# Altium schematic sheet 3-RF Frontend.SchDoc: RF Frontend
size B; CompanyName: NGRF; Address1: 2130 Howard Drive W; Address2: North Mankato, MN 56003; Address3: www.nextgenrf.com; Revision: 2; SheetNumber: 3; SheetTotal: 7; ProjName: BytePipe X9002_HDK
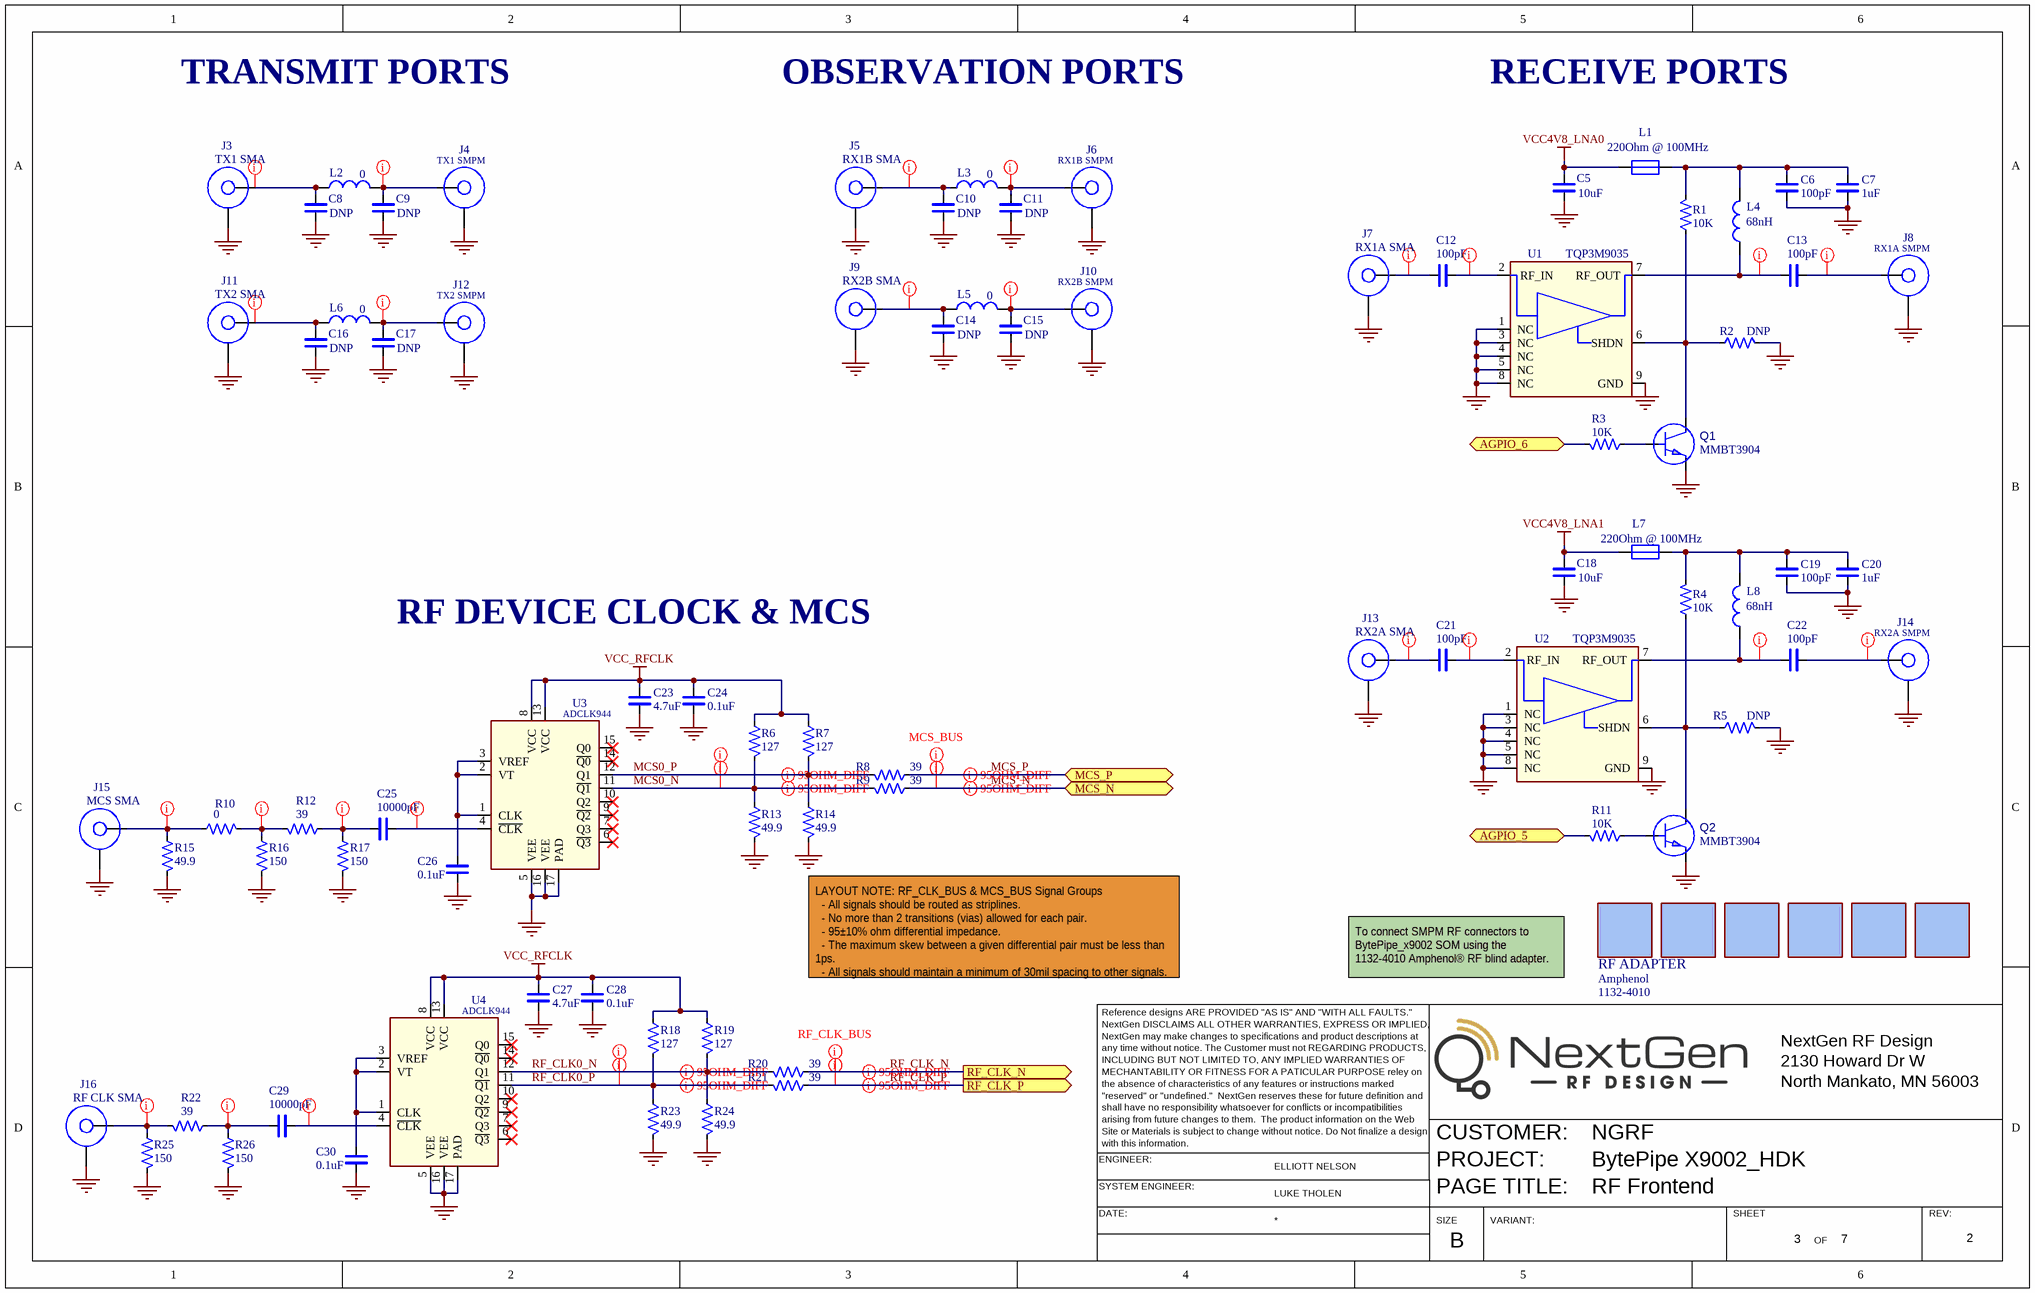
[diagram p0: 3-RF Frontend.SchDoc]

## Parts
B3  RF ADAPTER  OEM NAME: Amphenol  OEM#: 1132-4010
B4  RF ADAPTER  (value not drawn)
B5  RF ADAPTER  (value not drawn)
B6  RF ADAPTER  (value not drawn)
B7  RF ADAPTER  (value not drawn)
B8  RF ADAPTER  (value not drawn)
C5  value 10uF  [SM/0402/CAP]  (hidden comment: CAP_CERAMIC_0402)
C6  value 100pF  [SM/0402/CAP]  (hidden comment: CAP_CERAMIC_0402)
C7  value 1uF  [SM/0402/CAP]  (hidden comment: CAP_CERAMIC_0402)
C8  value DNP  [SM/0402/CAP]  (hidden comment: CAP_CERAMIC_0402)
C9  value DNP  [SM/0402/CAP]  (hidden comment: CAP_CERAMIC_0402)
C10  value DNP  [SM/0402/CAP]  (hidden comment: CAP_CERAMIC_0402)
C11  value DNP  [SM/0402/CAP]  (hidden comment: CAP_CERAMIC_0402)
C12  value 100pF  [SM/0402/CAP]  (hidden comment: CAP_CERAMIC_0402)
C13  value 100pF  [SM/0402/CAP]  (hidden comment: CAP_CERAMIC_0402)
C14  value DNP  [SM/0402/CAP]  (hidden comment: CAP_CERAMIC_0402)
C15  value DNP  [SM/0402/CAP]  (hidden comment: CAP_CERAMIC_0402)
C16  value DNP  [SM/0402/CAP]  (hidden comment: CAP_CERAMIC_0402)
C17  value DNP  [SM/0402/CAP]  (hidden comment: CAP_CERAMIC_0402)
C18  value 10uF  [SM/0402/CAP]  (hidden comment: CAP_CERAMIC_0402)
C19  value 100pF  [SM/0402/CAP]  (hidden comment: CAP_CERAMIC_0402)
C20  value 1uF  [SM/0402/CAP]  (hidden comment: CAP_CERAMIC_0402)
C21  value 100pF  [SM/0402/CAP]  (hidden comment: CAP_CERAMIC_0402)
C22  value 100pF  [SM/0402/CAP]  (hidden comment: CAP_CERAMIC_0402)
C23  value 4.7uF  [SM/0402/CAP]  (hidden comment: CAP_CERAMIC_0402)
C24  value 0.1uF  [SM/0402/CAP]  (hidden comment: CAP_CERAMIC_0402)
C25  value 10000pF  [SM/0402/CAP]  (hidden comment: CAP_CERAMIC_0402)
C26  value 0.1uF  [SM/0402/CAP]  (hidden comment: CAP_CERAMIC_0402)
C27  value 4.7uF  [SM/0402/CAP]  (hidden comment: CAP_CERAMIC_0402)
C28  value 0.1uF  [SM/0402/CAP]  (hidden comment: CAP_CERAMIC_0402)
C29  value 10000pF  [SM/0402/CAP]  (hidden comment: CAP_CERAMIC_0402)
C30  value 0.1uF  [SM/0402/CAP]  (hidden comment: CAP_CERAMIC_0402)
J3  value TX1 SMA  [SM/CON/RF/SMA/BRD-EDGE_C]  (hidden comment: CON_RF_SMA_BRD-EDGE_C)
J4  value TX1 SMPM  [SM/CON/RF/SMPM/VERT_A]  (hidden comment: CON_RF_SMPM_SMT_AMPHENOL)
J5  value RX1B SMA  [SM/CON/RF/SMA/BRD-EDGE_C]  (hidden comment: CON_RF_SMA_BRD-EDGE_C)
J6  value RX1B SMPM  [SM/CON/RF/SMPM/VERT_A]  (hidden comment: CON_RF_SMPM_SMT_AMPHENOL)
J7  value RX1A SMA  [SM/CON/RF/SMA/BRD-EDGE_C]  (hidden comment: CON_RF_SMA_BRD-EDGE_C)
J8  value RX1A SMPM  [SM/CON/RF/SMPM/VERT_A]  (hidden comment: CON_RF_SMPM_SMT_AMPHENOL)
J9  value RX2B SMA  [SM/CON/RF/SMA/BRD-EDGE_C]  (hidden comment: CON_RF_SMA_BRD-EDGE_C)
J10  value RX2B SMPM  [SM/CON/RF/SMPM/VERT_A]  (hidden comment: CON_RF_SMPM_SMT_AMPHENOL)
J11  value TX2 SMA  [SM/CON/RF/SMA/BRD-EDGE_C]  (hidden comment: CON_RF_SMA_BRD-EDGE_C)
J12  value TX2 SMPM  [SM/CON/RF/SMPM/VERT_A]  (hidden comment: CON_RF_SMPM_SMT_AMPHENOL)
J13  value RX2A SMA  [SM/CON/RF/SMA/BRD-EDGE_C]  (hidden comment: CON_RF_SMA_BRD-EDGE_C)
J14  value RX2A SMPM  [SM/CON/RF/SMPM/VERT_A]  (hidden comment: CON_RF_SMPM_SMT_AMPHENOL)
J15  value MCS SMA  [SM/CON/RF/SMA/BRD-EDGE_C]  (hidden comment: CON_RF_SMA_BRD-EDGE_C)
J16  value RF CLK SMA  [SM/CON/RF/SMA/BRD-EDGE_C]  (hidden comment: CON_RF_SMA_BRD-EDGE_C)
L1  value 220Ohm @ 100MHz  [SM/0603]  (hidden comment: FERRITE_0603_A)
L2  value 0  [SM/0402]  (hidden comment: IND_0402)
L3  value 0  [SM/0402]  (hidden comment: IND_0402)
L4  value 68nH  [SM/0603]  (hidden comment: IND_0603)
L5  value 0  [SM/0402]  (hidden comment: IND_0402)
L6  value 0  [SM/0402]  (hidden comment: IND_0402)
L7  value 220Ohm @ 100MHz  [SM/0603]  (hidden comment: FERRITE_0603_A)
L8  value 68nH  [SM/0603]  (hidden comment: IND_0603)
Q1  value MMBT3904  [SM/SOT23_A]  (hidden comment: TRANSISTOR_NPN_SOT23)
Q2  value MMBT3904  [SM/SOT23_A]  (hidden comment: TRANSISTOR_NPN_SOT23)
R1  value 10K  [SM/0402/RES]  (hidden comment: RES_0402_A)
R2  value DNP  [SM/0402/RES]  (hidden comment: RES_0402_A)
R3  value 10K  [SM/0402/RES]  (hidden comment: RES_0402_A)
R4  value 10K  [SM/0402/RES]  (hidden comment: RES_0402_A)
R5  value DNP  [SM/0402/RES]  (hidden comment: RES_0402_A)
R6  value 127  [SM/0402/RES]  (hidden comment: RES_0402_A)
R7  value 127  [SM/0402/RES]  (hidden comment: RES_0402_A)
R8  value 39  [SM/0402/RES]  (hidden comment: RES_0402_A)
R9  value 39  [SM/0402/RES]  (hidden comment: RES_0402_A)
R10  value 0  [SM/0402/RES]  (hidden comment: RES_0402_A)
R11  value 10K  [SM/0402/RES]  (hidden comment: RES_0402_A)
R12  value 39  [SM/0402/RES]  (hidden comment: RES_0402_A)
R13  value 49.9  [SM/0402/RES]  (hidden comment: RES_0402_A)
R14  value 49.9  [SM/0402/RES]  (hidden comment: RES_0402_A)
R15  value 49.9  [SM/0402/RES]  (hidden comment: RES_0402_A)
R16  value 150  [SM/0402/RES]  (hidden comment: RES_0402_A)
R17  value 150  [SM/0402/RES]  (hidden comment: RES_0402_A)
R18  value 127  [SM/0402/RES]  (hidden comment: RES_0402_A)
R19  value 127  [SM/0402/RES]  (hidden comment: RES_0402_A)
R20  value 39  [SM/0402/RES]  (hidden comment: RES_0402_A)
R21  value 39  [SM/0402/RES]  (hidden comment: RES_0402_A)
R22  value 39  [SM/0402/RES]  (hidden comment: RES_0402_A)
R23  value 49.9  [SM/0402/RES]  (hidden comment: RES_0402_A)
R24  value 49.9  [SM/0402/RES]  (hidden comment: RES_0402_A)
R25  value 150  [SM/0402/RES]  (hidden comment: RES_0402_A)
R26  value 150  [SM/0402/RES]  (hidden comment: RES_0402_A)
U1  value TQP3M9035  [SM/DFN8/2X2MM_E]  (hidden comment: IC_TQP3M9035_DFN-8)
U2  value TQP3M9035  [SM/DFN8/2X2MM_E]  (hidden comment: IC_TQP3M9035_DFN-8)
U3  value ADCLK944  [SM/QFN16/3X3/0.5LS_A]  (hidden comment: IC_ADCLK944_QFN16)
U4  value ADCLK944  [SM/QFN16/3X3/0.5LS_A]  (hidden comment: IC_ADCLK944_QFN16)

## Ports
AGPIO_5 (bidir), AGPIO_6 (bidir), MCS_N (bidir), MCS_P (bidir), RF_CLK_N (out), RF_CLK_P (out)

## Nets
GND: C5.2(N2) C6.2(N2) C7.2(N2) C8.2(N2) C9.2(N2) C10.2(N2) C11.2(N2) C14.2(N2) C15.2(N2) C16.2(N2) C17.2(N2) C18.2(N2) C19.2(N2) C20.2(N2) C23.2(N2) C24.2(N2) C26.2(N2) C27.2(N2) C28.2(N2) C30.2(N2) J3.2 J4.2 J5.2 J6.2 J7.2 J8.2 J9.2 J10.2 J11.2 J12.2 J13.2 J14.2 J15.2 J16.2 Q1.2(E) Q2.2(E) R2.1 R5.1 R13.2 R14.2 R15.2 R16.2 R17.2 R23.2 R24.2 R25.2 R26.2 U1.1(NC) U1.3(NC) U1.4(NC) U1.5(NC) U1.8(NC) U1.9(GND) U2.1(NC) U2.3(NC) U2.4(NC) U2.5(NC) U2.8(NC) U2.9(GND) U3.5(VEE) U3.16(VEE) U3.17(PAD) U4.5(VEE) U4.16(VEE) U4.17(PAD)
VCC4V8_LNA0: C5.1(N1) L1.1(PIN1)
VCC4V8_LNA1: C18.1(N1) L7.1(PIN1)
VCC_RFCLK: C23.1(N1) C24.1(N1) C27.1(N1) C28.1(N1) R6.1 R7.1 R18.1 R19.1 U3.8(VCC) U3.13(VCC) U4.8(VCC) U4.13(VCC)
AGPIO_5: R11.1 ; port AGPIO_5
AGPIO_6: R3.1 ; port AGPIO_6
MCS0_N: R6.2 R9.2 R13.1 U3.11(~{Q1})
MCS0_P: R7.2 R8.2 R14.1 U3.12(Q1)
MCS_N: R9.1 ; port MCS_N
MCS_P: R8.1 ; port MCS_P
RF_CLK0_N: R19.2 R20.2 R24.1 U4.12(Q1)
RF_CLK0_P: R18.2 R21.2 R23.1 U4.11(~{Q1})
RF_CLK_N: R20.1 ; port RF_CLK_N
RF_CLK_P: R21.1 ; port RF_CLK_P
NetC6_1: C6.1(N1) C7.1(N1) L1.2(PIN2) L4.2(PIN2) R1.1
NetC8_1: C8.1(N1) J3.1 L2.1(PIN1)
NetC9_1: C9.1(N1) J4.1 L2.2(PIN2)
NetC10_1: C10.1(N1) J5.1 L3.1(PIN1)
NetC11_1: C11.1(N1) J6.1 L3.2(PIN2)
NetC12_1: C12.1(N1) J7.1
NetC12_2: C12.2(N2) U1.2(RF_IN)
NetC13_1: C13.1(N1) L4.1(PIN1) U1.7(RF_OUT)
NetC13_2: C13.2(N2) J8.1
NetC14_1: C14.1(N1) J9.1 L5.1(PIN1)
NetC15_1: C15.1(N1) J10.1 L5.2(PIN2)
NetC16_1: C16.1(N1) J11.1 L6.1(PIN1)
NetC17_1: C17.1(N1) J12.1 L6.2(PIN2)
NetC19_1: C19.1(N1) C20.1(N1) L7.2(PIN2) L8.2(PIN2) R4.1
NetC21_1: C21.1(N1) J13.1
NetC21_2: C21.2(N2) U2.2(RF_IN)
NetC22_1: C22.1(N1) L8.1(PIN1) U2.7(RF_OUT)
NetC22_2: C22.2(N2) J14.1
NetC25_1: C25.1(N1) R12.1 R17.1
NetC25_2: C25.2(N2) U3.4(~{CLK})
NetC26_1: C26.1(N1) U3.1(CLK) U3.2(VT) U3.3(VREF)
NetC29_1: C29.1(N1) R22.1 R26.1
NetC29_2: C29.2(N2) U4.4(~{CLK})
NetC30_1: C30.1(N1) U4.1(CLK) U4.2(VT) U4.3(VREF)
NetJ15_1: J15.1 R10.2 R15.1
NetJ16_1: J16.1 R22.2 R25.1
NetQ1_1: Q1.1(B) R3.2
NetQ1_3: Q1.3(C) R1.2 R2.2 U1.6(SHDN)
NetQ2_1: Q2.1(B) R11.2
NetQ2_3: Q2.3(C) R4.2 R5.2 U2.6(SHDN)
NetR10_1: R10.1 R12.2 R16.1

Not connected (* = marked no-connect by the designer): U3 6(~{Q3})* 7(Q3)* 9(~{Q2})* 10(Q2)* 14(~{Q0})* 15(Q0)*; U4 6(~{Q3})* 7(Q3)* 9(~{Q2})* 10(Q2)* 14(~{Q0})* 15(Q0)*

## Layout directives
net class 50OHM_SE: NetC8_1, NetC9_1, NetC10_1, NetC11_1, NetC12_1, NetC12_2, NetC13_1, NetC13_2, NetC14_1, NetC15_1, NetC16_1, NetC17_1, NetC21_1, NetC21_2, NetC22_1, NetC22_2, NetC25_1, NetC25_2, NetC29_1, NetC29_2, NetJ15_1, NetJ16_1, NetR10_1
differential pair; Impedance: 90 Ohms; differential pair class 95OHM_DIFF: MCS0_N, MCS0_P, MCS_N, MCS_P, RF_CLK0_N, RF_CLK0_P, RF_CLK_N, RF_CLK_P
net class RF_CLK_BUS: RF_CLK0_N, RF_CLK0_P, RF_CLK_N, RF_CLK_P
net class MCS_BUS: MCS0_N, MCS0_P, MCS_N, MCS_P

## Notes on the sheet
- TRANSMIT PORTS
- OBSERVATION PORTS
- RECEIVE PORTS
- RF DEVICE CLOCK & MCS
- (near R14) LAYOUT NOTE: RF_CLK_BUS & MCS_BUS Signal Groups
  - All signals should be routed as striplines.
  - No more than 2 transitions (vias) allowed for each pair.
  - 95±10% ohm differential impedance.
  - The maximum skew between a given differential pair must be less than 1ps.
  - All signals should maintain a minimum of 30mil spacing to other signals.
- (near B3) To connect SMPM RF connectors to BytePipe_x9002 SOM using the 1132-4010 Amphenol® RF blind adapter.
- Reference designs ARE PROVIDED "AS IS" AND "WITH ALL FAULTS."
- NextGen DISCLAIMS ALL OTHER WARRANTIES, EXPRESS OR IMPLIED,
- NextGen may make changes to specifications and product descriptions at
- NextGen RF Design
- any time without notice. The Customer must not REGARDING PRODUCTS,
- INCLUDING BUT NOT LIMITED TO, ANY IMPLIED WARRANTIES OF
- MECHANTABILITY OR FITNESS FOR A PATICULAR PURPOSE reley on
- "reserved" or "undefined."  NextGen reserves these for future definition and
- the absence of characteristics of any features or instructions marked
- shall have no responsibility whatsoever for conflicts or incompatibilities
- 2130 Howard Dr W
- North Mankato, MN 56003
- ENGINEER:
- Site or Materials is subject to change without notice. Do Not finalize a design
- with this information.
- arising from future changes to them.  The product information on the Web
- ELLIOTT NELSON
- CUSTOMER:
- PROJECT:
- SYSTEM ENGINEER:
- DATE:
- LUKE THOLEN
- SIZE
- PAGE TITLE:
- VARIANT:
- SHEET
- OF
- REV:
- B

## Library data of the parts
B3 = BOM_COMPONENT_NO-FOOTPRINT: Amphenol® RF SMPM blind adapter
B4-B8 = BOM_COMPONENT_NO-FOOTPRINT: Amphenol® RF SMPM blind adapter; OEM#: 1132-4010
C5 C18 = CAP_CERAMIC_0402: 10µF ±20% 10V Ceramic Capacitor X5R 0402 (1005 Metric); OEM#: CL05A106MP8NUB8; OEM NAME: Samsung
C6 C12 C13 C19 C21 C22 = CAP_CERAMIC_0402: CAP CER 100PF 50V C0G/NP0 0402; TOL: ±5%; OEM#: CL05C101JB5NNNC; OEM NAME: Samsung
C7 C20 = CAP_CERAMIC_0402: CAP CER 1UF 16V X5R 0402; TOL: ±10%; OEM#: CL05A105KO5NNNC; OEM NAME: Samsung
C23 C27 = CAP_CERAMIC_0402: CAP CER 4.7UF 10V X5R 0402; TOL: ±20%; OEM#: CL05A475MP5NRNC; OEM NAME: Samsung
C24 C26 C28 C30 = CAP_CERAMIC_0402: CAP CER 0.1UF 25V X7R 0402; TOL: ±10%; OEM#: CL05B104KA5NNNC; OEM NAME: Samsung
C25 C29 = CAP_CERAMIC_0402: CAP CER 10000PF 50V X7R 0402; TOL: ±10%; OEM#: CL05B103KB5VPNC; OEM NAME: Samsung
J3 J5 J7 J9 J11 J13 J15 J16 = CON_RF_SMA_BRD-EDGE_C: SMA board edge style, .250" wide style; OEM#: 142-0711-821; OEM NAME: Cinch
J4 J6 J8 J10 J12 J14 = CON_RF_SMPM_SMT_AMPHENOL: SMPM Connector Plug, Male Pin 50Ohm Surface Mount Solder. Based off of Amphenol 925-144J-51PT; OEM NAME: AMP
L1 L7 = FERRITE_0603_A: 120 Ohms @ 100MHz 1 Power Line Ferrite Bead 0603 (1608 Metric) 3A 25mOhm; OEM#: BLM18SG221TN1D; OEM NAME: Murata Electronics
L2 L3 L5 L6 = IND_0402: RES SMD 0 OHM JUMPER 1/10W 0402; OEM#: ERJ-2GE0R00X; OEM NAME: Panasonic
L4 L8 = IND_0603: FIXED IND 68NH 300MA 800 MOHM; OEM#: LQG18HH68NJ00D; OEM NAME: Murata
Q1 Q2 = TRANSISTOR_NPN_SOT23: Bipolar (BJT) Transistor NPN 40V 200mA 300MHz 300mW Surface Mount SOT-23-3 (TO-236); OEM#: MMBT3904LT1G; OEM NAME: ON Semiconductor
R1 R3 R4 R11 = RES_0402_A: RES SMD 10K OHM 1% 1/10W 0402; OEM#: ERJ-2RKF1002X; OEM NAME: Panasonic
R6 R7 R18 R19 = RES_0402_A: RES SMD 127 OHM 1% 1/10W 0402; OEM#: ERJ-2RKF1270X; OEM NAME: Panasonic
R8 R9 R12 R20-R22 = RES_0402_A: RES SMD 39 OHM 1% 1/10W 0402; OEM#: ERJ-2RKF39R0X; OEM NAME: Panasonic
R10 = RES_0402_A: RES SMD 0 OHM JUMPER 1/10W 0402; OEM#: ERJ-2GE0R00X; OEM NAME: Panasonic; TOL: 1%
R13-R15 R23 R24 = RES_0402_A: RES 49.9 OHM 1% 1/10W 0402; OEM#: ERJ-2RKF49R9X; OEM NAME: Panasonic
R16 R17 R25 R26 = RES_0402_A: RES SMD 150 OHM 1% 1/10W 0402; OEM#: ERJ-2RKF1500X; OEM NAME: Panasonic
U1 U2 = IC_TQP3M9035_DFN-8: RF Amplifier 50-4000MHz NF .66dB Gain 16.5dB @1.9GHz; OEM NAME: Qorvo
U3 U4 = IC_ADCLK944_QFN16: IC CLK BUFFER 1:4 7GHZ 16LFCSP; OEM#: ADCLK944BCPZ-R2; OEM NAME: ANALOG DEVICES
